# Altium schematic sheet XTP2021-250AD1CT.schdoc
size 127 x 101 mm
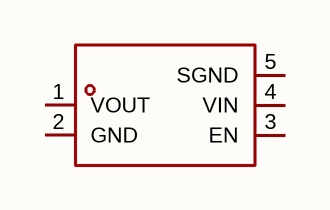
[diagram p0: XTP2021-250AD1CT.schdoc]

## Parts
U?  xtp2021-250ad1ct  [DFN-4_L1.0-W1.0-EP0.48]  (value not drawn)

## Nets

Not connected (* = marked no-connect by the designer): U? 1(VOUT) 2(GND) 3(EN) 4(VIN) 5(SGND)

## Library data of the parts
U? = xtp2021-250ad1ct: 输出极性:正极;工作电压:6.5V;输出电压:2.5V;输出电流:300mA;电源纹波抑制比(PSRR):75dB@(1kHz);输出类型:固定;; Manufacturer: XTX(芯天下); AddInBom: yes; ModelId: 6ec0b8c97ac644a1836116329de83799; ModelTransform: 40.1574,39.37,0,0,0,0,0,0,0; Output Configuration: 正极; Voltage - Supply: 6.5V; Output Voltage: 2.5V; Output Current: 300mA; standby current: 1uA; Noise: 67uVrms; Output Type: 固定; Number of Outputs: 1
